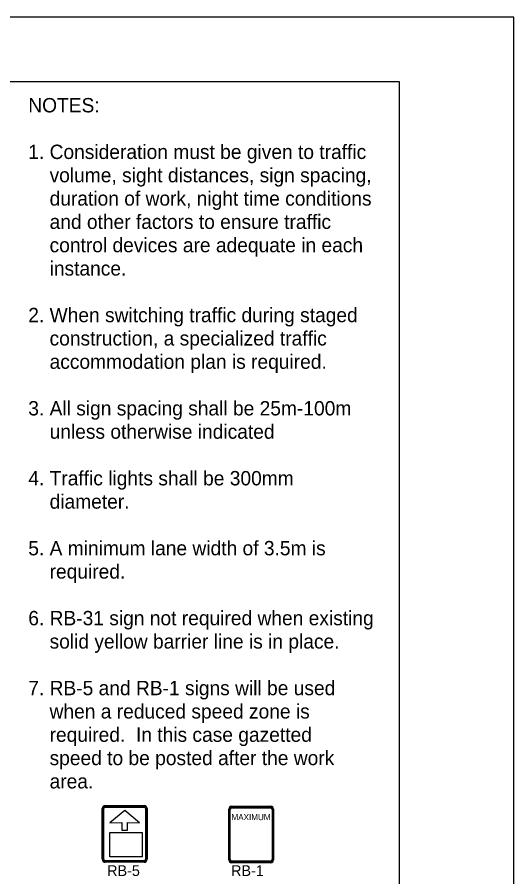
# Model space of a CAD drawing. Extents: x 1062 to 1288, y 239 to 518.
# Drawn here: x 1204.5 to 1287.6, y 374.1 to 517.9 of the extents above; entities that cross this region are included whole.
import ezdxf

# ---------------------------------------------------------------- set-up
doc = ezdxf.new("R2010")
doc.units = 0
for name, color, linetype in [('Level 17', 7, 'Continuous'), ('Level 36', 7, 'Continuous'), ('Level 60', 7, 'Continuous')]:
    doc.layers.add(name, color=color, linetype=linetype)

msp = doc.modelspace()

# ---------------------------------------------------------------- linework, layer by layer
at = {"layer": 'Level 17'}
for p, q in [((1218.7, 377.06), (1218.7, 385.53)), ((1218.83, 377.06), (1218.83, 385.53)), ((1218.95, 377.06), (1218.95, 385.53)), ((1219.21, 386.03), (1225.7, 386.03)), ((1219.21, 386.03), (1219.21, 386.03)), ((1219.21, 385.9), (1225.7, 385.91)), ((1219.21, 385.91), (1219.21, 385.9)), ((1219.21, 385.78), (1225.7, 385.78)), ((1219.21, 385.78), (1219.21, 385.78)), ((1225.95, 385.53), (1225.95, 377.06)), ((1226.08, 385.53), (1226.08, 377.06)), ((1226.2, 385.53), (1226.2, 377.06)), ((1239.86, 376.97), (1239.86, 385.44)), ((1239.99, 376.97), (1239.99, 385.44)), ((1240.11, 376.97), (1240.11, 385.44)), ((1240.14, 385.84), (1240.14, 385.84)), ((1240.25, 385.89), (1240.25, 385.89)), ((1240.36, 385.94), (1240.37, 385.94)), ((1240.37, 385.94), (1246.86, 385.94)), ((1240.37, 385.82), (1246.86, 385.82)), ((1240.37, 385.69), (1246.86, 385.69)), ((1247.11, 385.44), (1247.11, 376.97)), ((1247.24, 385.44), (1247.24, 376.97)), ((1247.36, 385.44), (1247.36, 376.97)), ((1225.7, 376.81), (1219.21, 376.81)), ((1225.7, 376.68), (1219.21, 376.68)), ((1225.7, 376.56), (1219.21, 376.56)), ((1246.86, 376.72), (1240.37, 376.72)), ((1246.86, 376.59), (1240.37, 376.59)), ((1246.86, 376.47), (1240.37, 376.47))]:
    msp.add_line(p, q, dxfattribs=at)
msp.add_lwpolyline([(1219.94, 381.56), (1225.4, 381.56), (1225.4, 377.47), (1219.94, 377.47)], close=True, dxfattribs=at)
for centre, radius, start, end in [((1219.21, 385.53), 0.501, 90, 180), ((1219.21, 385.53), 0.376, 90, 180), ((1219.21, 385.53), 0.251, 90, 180), ((1225.7, 385.53), 0.501, 0, 90), ((1225.7, 385.53), 0.376, 0, 90), ((1225.7, 385.53), 0.251, 0, 90), ((1240.37, 385.44), 0.501, 90, 180), ((1240.37, 385.44), 0.376, 90, 180), ((1240.37, 385.44), 0.251, 90, 180), ((1246.86, 385.44), 0.501, 0, 90), ((1246.86, 385.44), 0.376, 0, 90), ((1246.86, 385.44), 0.251, 0, 90), ((1219.21, 377.06), 0.501, 180, 270), ((1219.21, 377.06), 0.376, 180, 270), ((1219.21, 377.06), 0.251, 180, 270), ((1225.7, 377.06), 0.501, 270, 0), ((1225.7, 377.06), 0.376, 270, 0), ((1225.7, 377.06), 0.251, 270, 0), ((1240.37, 376.97), 0.501, 180, 270), ((1240.37, 376.97), 0.376, 180, 270), ((1240.37, 376.97), 0.251, 180, 270), ((1246.86, 376.97), 0.501, 270, 0), ((1246.86, 376.97), 0.376, 270, 0), ((1246.86, 376.97), 0.251, 270, 0)]:
    msp.add_arc(centre, radius, start, end, dxfattribs=at)
at = {"layer": 'Level 36'}
for p, q in [((1222.45, 385.22), (1219.98, 383.14)), ((1224.93, 383.14), (1222.45, 385.22)), ((1219.98, 383.14), (1221.96, 383.24)), ((1221.96, 383.24), (1221.96, 381.92)), ((1222.95, 381.92), (1222.95, 383.24)), ((1222.95, 383.24), (1224.93, 383.14)), ((1221.96, 381.92), (1222.94, 381.92))]:
    msp.add_line(p, q, dxfattribs=at)
at = {"layer": 'Level 60'}
msp.add_line((1277.67, 517.93), (1277.67, 517.93), dxfattribs=at)
for points in [[(1287.56, 517.93), (1071.56, 517.93), (1071.56, 238.93), (1287.56, 238.93)], [(1268.44, 507.12), (1081.56, 507.12), (1081.56, 249.74), (1268.44, 249.74)]]:
    msp.add_lwpolyline(points, close=True, dxfattribs=at)

# ---------------------------------------------------------------- texts
at = {"layer": 'Level 17'}
for s, height, p in [('MAXIMUM', 1.012, (1240.32, 383.61)), ('RB-5', 1.8, (1219.51, 374.26)), ('RB-1', 1.8, (1240.25, 374.26))]:
    msp.add_text(s, height=height, dxfattribs=at).set_placement(p)
at = {"layer": 'Level 60'}
for s, p in [('NOTES:', (1206.32, 502.01)), ('1. Consideration must be given to traffic ', (1206.32, 494.21)), ('    volume, sight distances, sign spacing, ', (1206.32, 490.31)), ('    duration of work, night time conditions ', (1206.32, 486.41)), ('    and other factors to ensure traffic ', (1206.32, 482.51)), ('    control devices are adequate in each ', (1206.32, 478.61)), ('    instance.', (1206.32, 474.71)), ('2. When switching traffic during staged ', (1206.32, 466.91)), ('    construction, a specialized traffic ', (1206.32, 463.01)), ('    accommodation plan is required.', (1206.32, 459.11)), ('3. All sign spacing shall be 25m-100m ', (1206.32, 451.31)), ('    unless otherwise indicated', (1206.32, 447.41)), ('4. Traffic lights shall be 300mm ', (1206.32, 439.61)), ('    diameter.', (1206.32, 435.71)), ('5. A minimum lane width of 3.5m is ', (1206.32, 427.91)), ('    required.', (1206.32, 424.01)), ('6. RB-31 sign not required when existing ', (1206.32, 416.21)), ('    solid yellow barrier line is in place.', (1206.32, 412.31)), ('7. RB-5 and RB-1 signs will be used ', (1206.32, 404.51)), ('    when a reduced speed zone is  ', (1206.32, 400.61)), ('    required.  In this case gazetted ', (1206.32, 396.71)), ('    speed to be posted after the work ', (1206.32, 392.81)), ('    area.', (1206.32, 388.91))]:
    msp.add_text(s, height=2.4, dxfattribs=at).set_placement(p)

doc.saveas('drawing.dxf')
